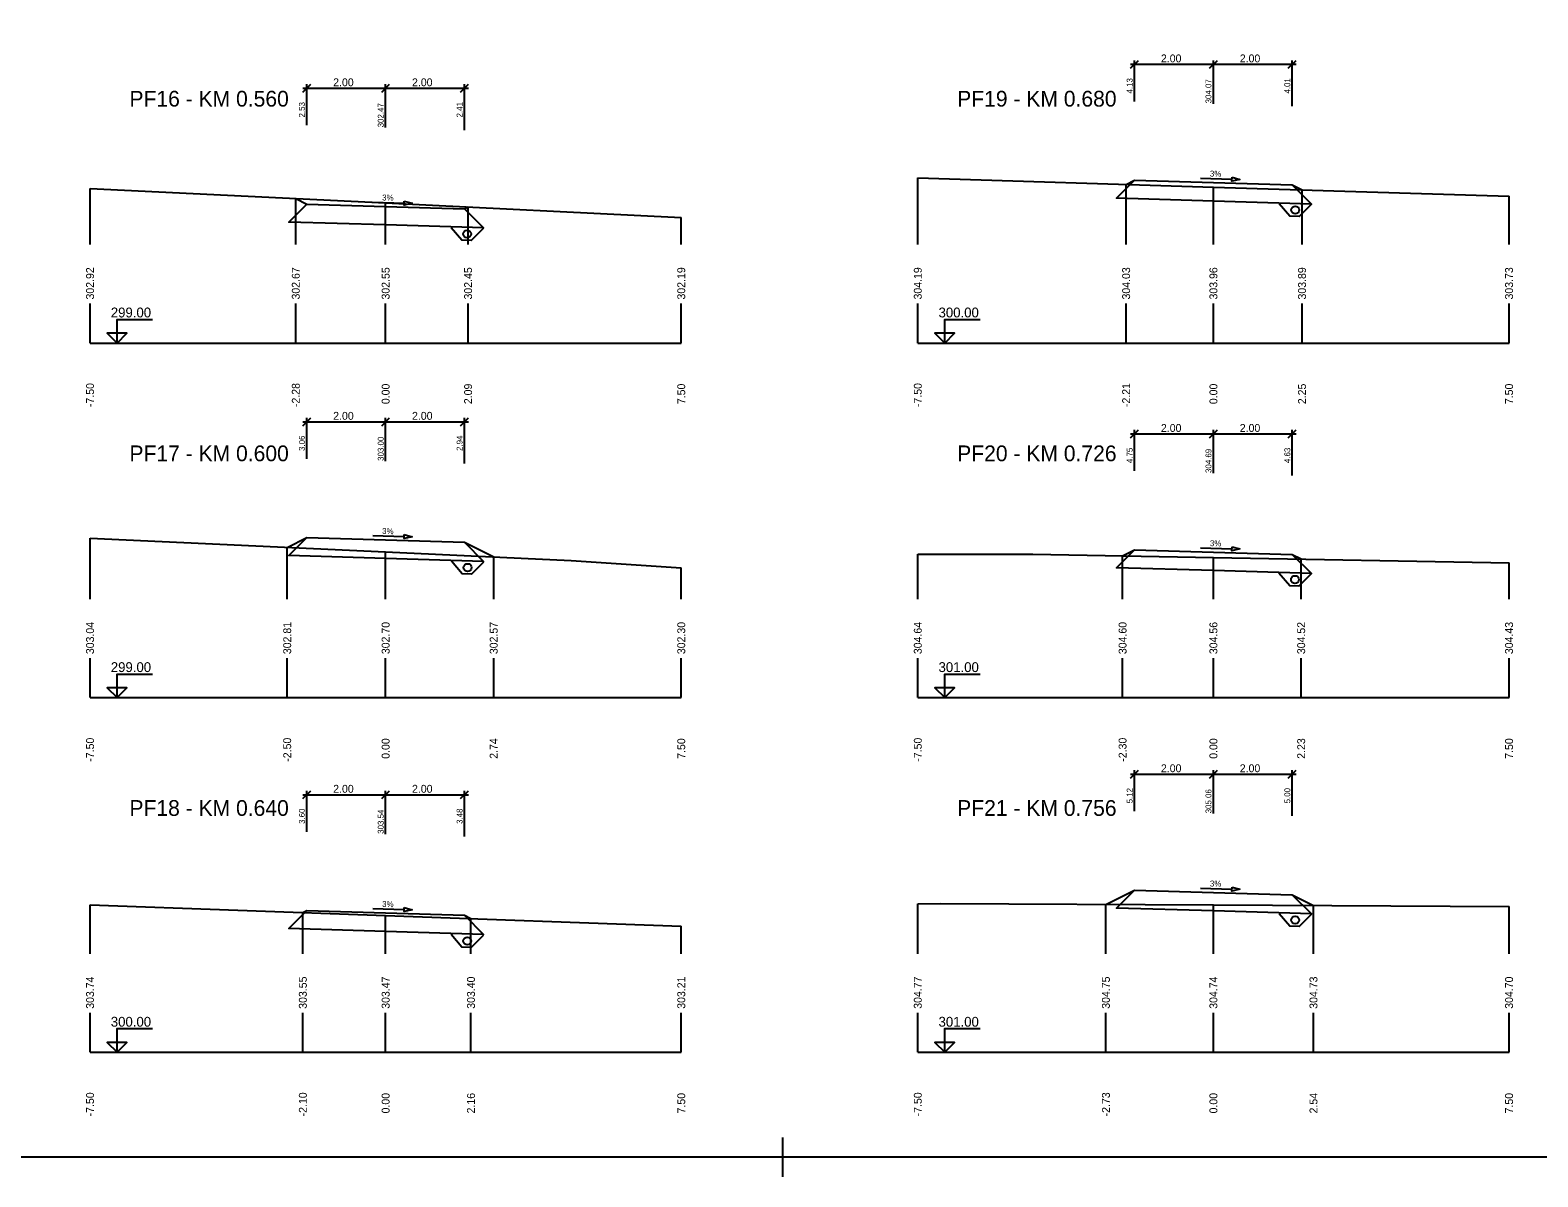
# Model space of a CAD drawing. Extents: x -9 to 2311, y -2 to 597.
# Drawn here: x 1064.8 to 1447.3, y -1.6 to 289.4 of the extents above; entities that cross this region are included whole.
import ezdxf

# ---------------------------------------------------------------- set-up
doc = ezdxf.new("R2010")
doc.units = 0
for name, color, linetype in [('KOTA', 7, 'Continuous'), ('KOTA_DELKY', 7, 'Continuous'), ('KOTA_DELKY_CONT', 7, 'Continuous'), ('NS_TELESO_VOZOVKY', 7, 'Continuous'), ('NS_V_PF', 7, 'Continuous'), ('REZY_PF_PUVODNI', 7, 'Continuous'), ('SESTAVY_REZU_PF', 7, 'Continuous'), ('SKLON', 7, 'Continuous'), ('SVK', 7, 'Continuous')]:
    doc.layers.add(name, color=color, linetype=linetype)

msp = doc.modelspace()

# ---------------------------------------------------------------- linework, layer by layer
for p, q in [((1255.65, 8.39), (1255.65, -1.61)), ((1255.65, 8.39), (1255.65, -1.61)), ((1255.65, 8.39), (1255.65, -1.61)), ((1255.65, 8.39), (1255.65, -1.61)), ((1255.65, 8.39), (1255.65, -1.61)), ((1255.65, 8.39), (1255.65, -1.61)), ((1255.65, 8.39), (1255.65, -1.61)), ((1255.65, 8.39), (1255.65, -1.61)), ((1255.65, 8.39), (1255.65, -1.61)), ((1255.65, 8.39), (1255.65, -1.61)), ((1255.65, 8.39), (1255.65, -1.61)), ((1255.65, 8.39), (1255.65, -1.61)), ((1260.65, 3.39), (1250.65, 3.39)), ((1260.65, 3.39), (1250.65, 3.39)), ((1260.65, 3.39), (1250.65, 3.39)), ((1260.65, 3.39), (1250.65, 3.39)), ((1260.65, 3.39), (1250.65, 3.39)), ((1260.65, 3.39), (1250.65, 3.39)), ((1260.65, 3.39), (1250.65, 3.39)), ((1260.65, 3.39), (1250.65, 3.39)), ((1260.65, 3.39), (1250.65, 3.39)), ((1260.65, 3.39), (1250.65, 3.39)), ((1260.65, 3.39), (1250.65, 3.39)), ((1260.65, 3.39), (1250.65, 3.39))]:
    msp.add_line(p, q)
msp.add_lwpolyline([(-4.35, 597.39), (2305.65, 597.39), (2305.65, 3.39), (-4.35, 3.39)], close=True)
for points in [[(1389.83, 245.16), (1386.77, 242.13), (1384.43, 242.23), (1381.72, 245.36)], [(1179.73, 239.07), (1176.68, 236.03), (1174.33, 236.13), (1171.62, 239.27)], [(1179.84, 154.4), (1176.79, 151.36), (1174.44, 151.46), (1171.73, 154.6)], [(1389.74, 151.36), (1386.69, 148.32), (1384.35, 148.42), (1381.64, 151.56)], [(1389.8, 64.97), (1386.75, 61.93), (1384.4, 62.03), (1381.7, 65.17)], [(1179.75, 59.66), (1176.7, 56.62), (1174.35, 56.72), (1171.64, 59.86)]]:
    msp.add_lwpolyline(points)
for centre in [(1385.77, 243.76), (1175.67, 237.67), (1175.78, 153), (1385.69, 149.96), (1385.74, 63.57), (1175.69, 58.25)]:
    msp.add_circle(centre, 1)
at = {"layer": 'KOTA'}
for points in [[(1086.85, 212.5), (1084.35, 212.5), (1086.85, 210), (1086.85, 216), (1095.85, 216)], [(1296.85, 212.5), (1294.35, 212.5), (1296.85, 210), (1296.85, 216), (1305.85, 216)], [(1086.85, 210), (1089.35, 212.5), (1086.85, 212.5)], [(1296.85, 210), (1299.35, 212.5), (1296.85, 212.5)], [(1086.85, 122.5), (1084.35, 122.5), (1086.85, 120), (1086.85, 126), (1095.85, 126)], [(1086.85, 120), (1089.35, 122.5), (1086.85, 122.5)], [(1296.85, 122.5), (1294.35, 122.5), (1296.85, 120), (1296.85, 126), (1305.85, 126)], [(1296.85, 120), (1299.35, 122.5), (1296.85, 122.5)], [(1086.85, 32.5), (1084.35, 32.5), (1086.85, 30), (1086.85, 36), (1095.85, 36)], [(1296.85, 32.5), (1294.35, 32.5), (1296.85, 30), (1296.85, 36), (1305.85, 36)], [(1086.85, 30), (1089.35, 32.5), (1086.85, 32.5)], [(1296.85, 30), (1299.35, 32.5), (1296.85, 32.5)]]:
    msp.add_lwpolyline(points, dxfattribs=at)
at = {"layer": 'KOTA_DELKY'}
for points in [[(1344, 279.73), (1346, 281.73)], [(1344, 280.73), (1366, 280.73)], [(1345, 271.33), (1345, 281.73)], [(1364, 279.73), (1366, 281.73)], [(1364, 279.73), (1366, 281.73)], [(1364, 280.73), (1386, 280.73)], [(1365, 270.73), (1365, 281.73)], [(1365, 270.73), (1365, 281.73)], [(1384, 279.73), (1386, 281.73)], [(1385, 270.13), (1385, 281.73)], [(1134, 273.66), (1136, 275.66)], [(1135, 265.26), (1135, 275.66)], [(1154, 273.66), (1156, 275.66)], [(1154, 273.66), (1156, 275.66)], [(1155, 264.66), (1155, 275.66)], [(1155, 264.66), (1155, 275.66)], [(1174, 273.66), (1176, 275.66)], [(1175, 264.06), (1175, 275.66)], [(1134, 274.66), (1156, 274.66)], [(1154, 274.66), (1176, 274.66)], [(1134, 189.02), (1136, 191.02)], [(1134, 190.02), (1156, 190.02)], [(1135, 180.62), (1135, 191.02)], [(1154, 189.02), (1156, 191.02)], [(1154, 189.02), (1156, 191.02)], [(1154, 190.02), (1176, 190.02)], [(1155, 180.02), (1155, 191.02)], [(1155, 180.02), (1155, 191.02)], [(1174, 189.02), (1176, 191.02)], [(1175, 179.42), (1175, 191.02)], [(1344, 185.94), (1346, 187.94)], [(1345, 177.54), (1345, 187.94)], [(1364, 185.94), (1366, 187.94)], [(1364, 185.94), (1366, 187.94)], [(1365, 176.94), (1365, 187.94)], [(1365, 176.94), (1365, 187.94)], [(1384, 185.94), (1386, 187.94)], [(1385, 176.34), (1385, 187.94)], [(1344, 186.94), (1366, 186.94)], [(1364, 186.94), (1386, 186.94)], [(1344, 99.58), (1346, 101.58)], [(1344, 100.58), (1366, 100.58)], [(1345, 91.18), (1345, 101.58)], [(1364, 99.58), (1366, 101.58)], [(1364, 99.58), (1366, 101.58)], [(1364, 100.58), (1386, 100.58)], [(1365, 90.58), (1365, 101.58)], [(1365, 90.58), (1365, 101.58)], [(1384, 99.58), (1386, 101.58)], [(1385, 89.98), (1385, 101.58)], [(1134, 94.37), (1136, 96.37)], [(1135, 85.97), (1135, 96.37)], [(1154, 94.37), (1156, 96.37)], [(1154, 94.37), (1156, 96.37)], [(1155, 85.37), (1155, 96.37)], [(1155, 85.37), (1155, 96.37)], [(1174, 94.37), (1176, 96.37)], [(1175, 84.77), (1175, 96.37)], [(1134, 95.37), (1156, 95.37)], [(1154, 95.37), (1176, 95.37)]]:
    msp.add_lwpolyline(points, dxfattribs=at)
at = {"layer": 'NS_TELESO_VOZOVKY'}
for points in [[(1365, 250.73), (1385, 250.13), (1385, 250.13), (1389.85, 245.28), (1365, 246.03), (1340.44, 246.77), (1345, 251.33), (1345, 251.33), (1365, 250.73)], [(1155, 244.66), (1175, 244.06), (1175, 244.06), (1179.85, 239.22), (1155, 239.96), (1130.44, 240.7), (1135, 245.26), (1135, 245.26), (1155, 244.66)], [(1155, 160.02), (1175, 159.42), (1175, 159.42), (1179.85, 154.57), (1155, 155.32), (1130.44, 156.05), (1135, 160.62), (1135, 160.62), (1155, 160.02)], [(1365, 156.94), (1385, 156.34), (1385, 156.34), (1389.85, 151.49), (1365, 152.24), (1340.44, 152.98), (1345, 157.54), (1345, 157.54), (1365, 156.94)], [(1365, 70.58), (1385, 69.98), (1385, 69.98), (1389.85, 65.13), (1365, 65.88), (1340.44, 66.61), (1345, 71.18), (1345, 71.18), (1365, 70.58)], [(1155, 65.37), (1175, 64.77), (1175, 64.77), (1179.85, 59.93), (1155, 60.67), (1130.44, 61.41), (1135, 65.97), (1135, 65.97), (1155, 65.37)]]:
    msp.add_lwpolyline(points, dxfattribs=at)
at = {"layer": 'NS_V_PF'}
for points in [[(1342.86, 250.26), (1345, 251.33), (1345, 251.33), (1365, 250.73), (1385, 250.13), (1385, 250.13), (1387.48, 248.89)], [(1132.2, 246.66), (1135, 245.26), (1135, 245.26), (1155, 244.66), (1175, 244.06), (1175, 244.06), (1175.91, 244.52)], [(1130.03, 158.13), (1135, 160.62), (1135, 160.62), (1155, 160.02), (1175, 159.42), (1175, 159.42), (1182.41, 155.71)], [(1341.96, 156.02), (1345, 157.54), (1345, 157.54), (1365, 156.94), (1385, 156.34), (1385, 156.34), (1387.27, 155.2)], [(1337.73, 67.54), (1345, 71.18), (1345, 71.18), (1365, 70.58), (1385, 69.98), (1385, 69.98), (1390.39, 67.28)], [(1133.99, 65.47), (1135, 65.97), (1135, 65.97), (1155, 65.37), (1175, 64.77), (1175, 64.77), (1176.65, 63.95)]]:
    msp.add_lwpolyline(points, dxfattribs=at)
at = {"layer": 'REZY_PF_PUVODNI'}
for points in [[(1080, 249.22), (1155, 245.54), (1155, 245.54), (1230, 241.87)], [(1290, 251.89), (1365, 249.58), (1365, 249.58), (1440, 247.27)], [(1080, 160.45), (1155, 156.98), (1155, 156.98), (1202.07, 154.81), (1230, 152.96)], [(1290, 156.45), (1319.18, 156.43), (1365, 155.61), (1440, 154.25)], [(1080, 67.39), (1155, 64.72), (1155, 64.72), (1230, 62.05)], [(1290, 67.7), (1295.79, 67.75), (1365, 67.41), (1365, 67.41), (1440, 67.03)]]:
    msp.add_lwpolyline(points, dxfattribs=at)
at = {"layer": 'SESTAVY_REZU_PF'}
for points in [[(1080, 210), (1230, 210)], [(1290, 210), (1440, 210)], [(1080, 120), (1230, 120)], [(1290, 120), (1440, 120)], [(1080, 30), (1230, 30)], [(1290, 30), (1440, 30)]]:
    msp.add_lwpolyline(points, dxfattribs=at)
at = {"layer": 'SKLON'}
for points in [[(1361.71, 251.83), (1369.71, 251.59)], [(1369.73, 252.09), (1371.71, 251.53), (1369.7, 251.09), (1369.73, 252.09)], [(1151.71, 245.76), (1159.71, 245.52)], [(1159.73, 246.02), (1161.71, 245.46), (1159.7, 245.02), (1159.73, 246.02)], [(1151.71, 161.12), (1159.71, 160.88)], [(1159.73, 161.38), (1161.71, 160.82), (1159.7, 160.38), (1159.73, 161.38)], [(1361.71, 158.04), (1369.71, 157.8)], [(1369.73, 158.3), (1371.71, 157.74), (1369.7, 157.3), (1369.73, 158.3)], [(1361.71, 71.67), (1369.71, 71.43)], [(1369.73, 71.93), (1371.71, 71.37), (1369.7, 70.93), (1369.73, 71.93)], [(1151.71, 66.47), (1159.71, 66.23)], [(1159.73, 66.73), (1161.71, 66.17), (1159.7, 65.73), (1159.73, 66.73)]]:
    msp.add_lwpolyline(points, dxfattribs=at)
at = {"layer": 'SVK'}
for points in [[(1080, 235), (1080, 249.22)], [(1290, 235), (1290, 251.89)], [(1342.86, 235), (1342.86, 250.26)], [(1365, 235), (1365, 249.58)], [(1387.48, 235), (1387.48, 248.89)], [(1132.2, 235), (1132.2, 246.66)], [(1155, 235), (1155, 245.54)], [(1440, 235), (1440, 247.27)], [(1175.91, 235), (1175.91, 244.52)], [(1230, 235), (1230, 241.87)], [(1080, 210), (1080, 220)], [(1132.2, 210), (1132.2, 220)], [(1155, 210), (1155, 220)], [(1175.91, 210), (1175.91, 220)], [(1230, 210), (1230, 220)], [(1290, 210), (1290, 220)], [(1342.86, 210), (1342.86, 220)], [(1365, 210), (1365, 220)], [(1387.48, 210), (1387.48, 220)], [(1440, 210), (1440, 220)], [(1080, 145), (1080, 160.45)], [(1130.03, 145), (1130.03, 158.13)], [(1155, 145), (1155, 156.98)], [(1182.41, 145), (1182.41, 155.71)], [(1290, 145), (1290, 156.45)], [(1341.96, 145), (1341.96, 156.02)], [(1365, 145), (1365, 155.61)], [(1387.27, 145), (1387.27, 155.2)], [(1440, 145), (1440, 154.25)], [(1230, 145), (1230, 152.96)], [(1080, 120), (1080, 130)], [(1130.03, 120), (1130.03, 130)], [(1155, 120), (1155, 130)], [(1182.41, 120), (1182.41, 130)], [(1230, 120), (1230, 130)], [(1290, 120), (1290, 130)], [(1341.96, 120), (1341.96, 130)], [(1365, 120), (1365, 130)], [(1387.27, 120), (1387.27, 130)], [(1440, 120), (1440, 130)], [(1080, 55), (1080, 67.39)], [(1133.99, 55), (1133.99, 65.47)], [(1290, 55), (1290, 67.7)], [(1337.73, 55), (1337.73, 67.54)], [(1365, 55), (1365, 67.41)], [(1390.39, 55), (1390.39, 67.28)], [(1440, 55), (1440, 67.03)], [(1155, 55), (1155, 64.72)], [(1176.65, 55), (1176.65, 63.95)], [(1230, 55), (1230, 62.05)], [(1080, 30), (1080, 40)], [(1133.99, 30), (1133.99, 40)], [(1155, 30), (1155, 40)], [(1176.65, 30), (1176.65, 40)], [(1230, 30), (1230, 40)], [(1290, 30), (1290, 40)], [(1337.73, 30), (1337.73, 40)], [(1365, 30), (1365, 40)], [(1390.39, 30), (1390.39, 40)], [(1440, 30), (1440, 40)]]:
    msp.add_lwpolyline(points, dxfattribs=at)

# ---------------------------------------------------------------- texts
at = {"layer": 'KOTA'}
for s, p in [('299.00', (1085.27, 216.5)), ('300.00', (1295.27, 216.5)), ('299.00', (1085.27, 126.5)), ('301.00', (1295.27, 126.5)), ('300.00', (1085.27, 36.5)), ('301.00', (1295.27, 36.5))]:
    msp.add_text(s, height=2.5, dxfattribs=at).set_placement(p)
at = {"layer": 'KOTA_DELKY'}
for p in [(1351.69, 281.23), (1371.69, 281.23), (1141.69, 275.16), (1161.69, 275.16), (1141.69, 190.52), (1161.69, 190.52), (1351.69, 187.44), (1371.69, 187.44), (1351.69, 101.08), (1371.69, 101.08), (1141.69, 95.87), (1161.69, 95.87)]:
    msp.add_text('2.00', height=2, dxfattribs=at).set_placement(p)
at = {"layer": 'KOTA_DELKY_CONT'}
for s, p in [('4.13', (1344.5, 273.32)), ('304.07', (1364.5, 270.81)), ('4.01', (1384.5, 273.32)), ('2.53', (1134.5, 267.25)), ('302.47', (1154.5, 264.74)), ('2.41', (1174.5, 267.25)), ('3.06', (1134.5, 182.61)), ('303.00', (1154.5, 180.09)), ('2.94', (1174.5, 182.61)), ('4.75', (1344.5, 179.53)), ('304.69', (1364.5, 177.02)), ('4.63', (1384.5, 179.53)), ('5.12', (1344.5, 93.17)), ('305.06', (1364.5, 90.65)), ('5.00', (1384.5, 93.17)), ('3.60', (1134.5, 87.96)), ('303.54', (1154.5, 85.45)), ('3.48', (1174.5, 87.96))]:
    msp.add_text(s, height=1.5, rotation=90, dxfattribs=at).set_placement(p)
at = {"layer": 'SESTAVY_REZU_PF'}
for s, p in [('PF16 - KM 0.560', (1090, 270)), ('PF19 - KM 0.680', (1300, 270)), ('PF17 - KM 0.600', (1090, 180)), ('PF20 - KM 0.726', (1300, 180)), ('PF18 - KM 0.640', (1090, 90)), ('PF21 - KM 0.756', (1300, 90))]:
    msp.add_text(s, height=4, dxfattribs=at).set_placement(p)
at = {"layer": 'SKLON'}
for p in [(1364.09, 252.26), (1154.09, 246.19), (1154.09, 161.55), (1364.09, 158.47), (1364.09, 72.1), (1154.09, 66.9)]:
    msp.add_text('3%', height=1.5, rotation=358.2816, dxfattribs=at).set_placement(p)
at = {"layer": 'SVK'}
for s, p in [(' 302.92', (1081, 220.3)), (' 302.67', (1133.2, 220.3)), (' 302.55', (1156, 220.3)), (' 302.45', (1176.91, 220.3)), (' 302.19', (1231, 220.3)), (' 304.19', (1291, 220.3)), (' 304.03', (1343.86, 220.3)), (' 303.96', (1366, 220.3)), (' 303.89', (1388.48, 220.3)), (' 303.73', (1441, 220.3)), (' -7.50', (1081, 193)), (' -2.28', (1133.2, 193)), ('  0.00', (1156, 193)), ('  2.09', (1176.91, 193)), ('  7.50', (1231, 193)), (' -7.50', (1291, 193)), (' -2.21', (1343.86, 193)), ('  0.00', (1366, 193)), ('  2.25', (1388.48, 193)), ('  7.50', (1441, 193)), (' 303.04', (1081, 130.3)), (' 302.81', (1131.03, 130.3)), (' 302.70', (1156, 130.3)), (' 302.57', (1183.41, 130.3)), (' 302.30', (1231, 130.3)), (' 304.64', (1291, 130.3)), (' 304.60', (1342.96, 130.3)), (' 304.56', (1366, 130.3)), (' 304.52', (1388.27, 130.3)), (' 304.43', (1441, 130.3)), (' -7.50', (1081, 103)), (' -2.50', (1131.03, 103)), ('  0.00', (1156, 103)), ('  2.74', (1183.41, 103)), ('  7.50', (1231, 103)), (' -7.50', (1291, 103)), (' -2.30', (1342.96, 103)), ('  0.00', (1366, 103)), ('  2.23', (1388.27, 103)), ('  7.50', (1441, 103)), (' 303.74', (1081, 40.3)), (' 303.55', (1134.99, 40.3)), (' 303.47', (1156, 40.3)), (' 303.40', (1177.65, 40.3)), (' 303.21', (1231, 40.3)), (' 304.77', (1291, 40.3)), (' 304.75', (1338.73, 40.3)), (' 304.74', (1366, 40.3)), (' 304.73', (1391.39, 40.3)), (' 304.70', (1441, 40.3)), (' -7.50', (1081, 13)), (' -2.10', (1134.99, 13)), ('  0.00', (1156, 13)), ('  2.16', (1177.65, 13)), ('  7.50', (1231, 13)), (' -7.50', (1291, 13)), (' -2.73', (1338.73, 13)), ('  0.00', (1366, 13)), ('  2.54', (1391.39, 13)), ('  7.50', (1441, 13))]:
    msp.add_text(s, height=2, rotation=90, dxfattribs=at).set_placement(p)

doc.saveas('drawing.dxf')
